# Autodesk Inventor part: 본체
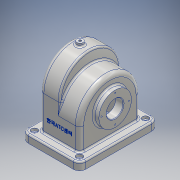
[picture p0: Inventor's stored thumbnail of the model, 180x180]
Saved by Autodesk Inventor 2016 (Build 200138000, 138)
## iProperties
Created: 2017-11
Part Number: 본체
Material: 알루미늄 6061
Document SubType Name: Modeling
Designer: USER
Density: 2.7 g/cm^3
Appearance: 알루미늄 - 평지
Mass: 1075.5 g
Surface Area: 1182.07 cm^2
Volume: 398.335 cm^3
Author: USER
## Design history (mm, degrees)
sketch "스케치1"
  geometry: L1 (-58, 0)-(-58, -80); L2 (58, 0)-(58, -80); L3 (58, -80)-(-58, -80); L4 (53, 0)-(53, -75); L5 (53, -75)-(-53, -75); L6 (-53, -75)-(-53, 0); A1 r 58 centre (0, 0) between (58, 0) and (-58, 0); A2 r 53 centre (0, 0) between (53, 0) and (-53, 0); 1 further point
  constraints: 12 end point, 4 point on circle, 2 centre point, 2 tangent, 2 vertical, 1 coincident, 3 other
  dimensions: "d0" = 116 diameter of A1; "d1" = 80 distance of L1.start L1.end; "d2" = 80 distance of L2.start L2.end; "d10" = 5 radial gap between concentric circles of A1 A2
node "작업 평면1"
extrude "돌출3" join sketch "스케치1" distance "d11" = 38; taper "d12" = 0 deg
sketch "스케치3"
  geometry: L1 (0, -58)-(80, -58) reference; L2 (0, -58)-(80, -58); L3 (80, 58)-(0, 58); L4 (80, 58)-(80, -58) reference; L5 (80, -58)-(80, 58); A1 r 58 centre (0, 0) between (0, 58) and (0, -58) reference; A2 r 58 centre (0, 0) between (0, 58) and (0, -58)
  constraints: 6 end point, 2 equal length, 2 point on circle, 2 point on line, 1 centre point, 1 coincident, 1 vertical
  dimensions: "d13" = 116 diameter of A2
extrude "돌출4" join sketch "스케치3" distance "d14" = 5; taper "d15" = 0 deg
sketch "스케치4"
  geometry: L1 (0, 58)-(-80, 58) reference; L2 (-80, 58)-(0, 58) reference; L3 (0, 58)-(-80, 58); L4 (0, -58)-(-80, -58) reference; L5 (-80, 58)-(-80, -58); L6 (-80, -58)-(0, -58); A1 r 58 centre (0, 0) between (0, -58) and (0, 58) reference; A2 r 58 centre (0, 0) between (0, -58) and (0, 58)
  constraints: 6 end point, 2 perpendicular, 2 point on circle, 2 point on line, 1 centre point, 1 coincident, 1 collinear
  dimensions: "d16" = 116 diameter of A2
extrude "돌출5" join sketch "스케치4" distance "d17" = 5; taper "d18" = 0 deg
sketch "스케치5"
  geometry: L1 (80, -58)-(80, 58) reference; L2 (80, -58)-(0, -58) reference; L3 (23, -58)-(80, -58); L4 (80, 58)-(80, -58) reference; L5 (80, -58)-(80, 58); L6 (80, 58)-(23, 58); L7 (0, 58)-(80, 58) reference; L8 (23, -53)-(75, -53); L9 (75, -53)-(75, 53); L10 (75, 53)-(23, 53); A1 r 58 centre (23, 0) between (23, 58) and (23, -58); A2 r 53 centre (23, 0) between (23, 53) and (23, -53)
  constraints: 12 end point, 4 point on circle, 2 centre point, 2 perpendicular, 2 point on line, 1 collinear, 1 tangent, 3 other
  dimensions: "d20" = 57 distance from line of A1.centre L1; "d21" = 58 radius of A1; "d22" = 5 radial gap between concentric circles of A1 A2
extrude "돌출6" join sketch "스케치5" distance "d23" = 38; taper "d24" = 0 deg
sketch "스케치6"
  geometry: L1 (23, -53)-(75, -53) reference; L2 (75, -53)-(75, 53) reference; L3 (75, 53)-(23, 53) reference; L4 (80, -58)-(0, -58) reference; L5 (0, 58)-(80, 58) reference; L6 (80, 58)-(80, -58) reference; L7 (80, -58)-(0, -58) reference; L8 (23, -58)-(80, -58); L9 (80, 58)-(23, 58); L10 (0, 58)-(80, 58) reference; L11 (80, 58)-(80, -58) reference; L12 (80, -58)-(80, 58); L13 (23, 53)-(75, 53); L14 (75, 53)-(75, -53); L15 (75, -53)-(23, -53); A1 r 53 centre (23, 0) between (23, 53) and (23, -53) reference; A2 r 58 centre (23, 0) between (23, 58) and (23, -58); A3 r 58 centre (0, 0) between (0, 58) and (0, -58) reference; A4 r 53 centre (23, 0) between (23, 53) and (23, -53); 1 further point
  constraints: 12 end point, 4 point on circle, 2 centre point, 2 point on line, 1 coincident, 1 collinear, 1 vertical, 3 other
  dimensions: "d25" = 116 diameter of A2; "d26" = 5 radial gap between concentric circles of A2 A4
extrude "돌출7" cut sketch "스케치6" distance "d27" = 5; taper "d28" = 0 deg
sketch "스케치7"
  geometry: L1 (80, -58)-(80, 58) reference; L2 (80, 58)-(23, 58) reference; L3 (0, -58)-(23, -58) reference; L4 (80, -58)-(0, -58) reference; L5 (23, -58)-(80, -58); L6 (80, -58)-(80, 58); L7 (23, 58)-(80, 58); A1 r 58 centre (23, 0) between (23, 58) and (23, -58) reference; A2 r 58 centre (23, 0) between (23, 58) and (23, -58); 1 further point
  constraints: 6 end point, 2 point on circle, 2 point on line, 1 centre point, 1 coincident, 1 collinear, 1 horizontal, 1 perpendicular
  dimensions: "d29" = 116 diameter of A2
extrude "돌출8" join sketch "스케치7" distance "d30" = 5; taper "d31" = 0 deg
sketch "스케치8"
  geometry: L1 (17, -17)-(-93, -17); L2 (-93, -17)-(-93, 133); L3 (-93, 133)-(17, 133); L4 (17, 133)-(17, -17); L5 (-5, 5)-(-71, 5); L6 (-71, 5)-(-71, 111); L7 (-71, 111)-(-5, 111); L8 (-5, 111)-(-5, 5); L9 (0, 116)-(0, 0) reference; L10 (0, 0)-(-76, 0) reference; L11 (-76, 0)-(-76, 116) reference; L12 (0, 116)-(-76, 116) reference; 10 further points
  constraints: 16 end point, 10 midpoint, 3 horizontal alignment, 3 vertical alignment, 2 parallel, 1 horizontal, 1 perpendicular
  dimensions: "d32" = 110 distance of L1.start L1.end; "d33" = 150 distance of L3.end L1.start; "d35" = 5 distance between parallel lines of L8 L9; "d36" = 5 distance between parallel lines of L10 L5
extrude "돌출9" join sketch "스케치8" distance "d37" = 15; taper "d38" = 0 deg
sketch "스케치9"
  geometry: L1 (88, 22)-(22, 22) reference; L2 (22, 22)-(22, 128) reference; L3 (88, 128)-(88, 22) reference; L4 (88, 128)-(22, 128) reference; L5 (22, 22)-(88, 22); L6 (88, 22)-(88, 128); L7 (88, 128)-(22, 128); L8 (22, 128)-(22, 22); 1 further point
  constraints: 8 end point, 2 parallel, 1 horizontal, 1 perpendicular
extrude "돌출10" cut sketch "스케치9" distance "d39" = 15; taper "d40" = 0 deg
node "작업 평면5"
  node "작업 평면4"
sketch "스케치10"
  geometry: C1 r 6 at (-74, 0); 1 further point
  constraints: 1 centre point, 1 horizontal alignment
  dimensions: "d42" = 12 diameter of C1; "d43" = 19 distance of point (-93, 0) C1.centre
extrude "돌출11" join sketch "스케치10" stored distance "d44" = 15; taper "d45" = 0 deg
sketch "스케치11"
  geometry: C1 r 6 at (0, 0) reference; 2 further points
  constraints: 1 coincident
hole "구멍1" sketch "스케치11" at (0, 0) diameter "d46" = 4.459; stored, may be unused: countersink angle "d50" = 90 deg, drill point angle "d52" = 118 deg; dims "d47" = 10, "d48" = 4, "d49" = 2, "d51" = 12.8
sketch "스케치13"
  geometry: L1 (80, -75)-(80, 75) reference; C1 r 31 at (15, 0); C2 r 16 at (15, 0); 1 further point
  constraints: 2 centre point, 1 coincident, 1 horizontal alignment
  dimensions: "d54" = 62 diameter of C1; "d55" = 32 diameter of C2; "d56" = 65 distance from line of C1.centre L1
extrude "돌출12" join sketch "스케치13" distance "d57" = 10; taper "d58" = 0 deg
sketch "스케치14"
  geometry: C1 r 16 at (0, 0) reference; C2 r 16 at (0, 0); 1 further point
  constraints: 1 centre point, 1 coincident
  dimensions: "d59" = 32 diameter of C2
extrude "돌출13" cut sketch "스케치14" distance "d60" = 85; taper "d61" = 0 deg
sketch "스케치15"
  geometry: L1 (-80, 75)-(-80, -75) reference; C1 r 37.5 at (-15, 0); C2 r 16 at (-15, 0); A1 r 58 centre (0, 0) between (0, -58) and (0, 58) reference
  constraints: 2 centre point, 1 coincident, 1 horizontal alignment
  dimensions: "d62" = 75 diameter of C1; "d63" = 32 diameter of C2; "d64" = 65 distance from line of C1.centre L1
extrude "돌출14" join sketch "스케치15" distance "d65" = 9; taper "d66" = 0 deg
sketch "스케치16"
  geometry: C1 r 16 at (0, 0) reference; 2 further points
  constraints: 1 horizontal alignment
  dimensions: "d67" = 26 distance of point (-26, 0) C1.centre
hole "구멍2" sketch "스케치16" at (-26, 0) diameter "d68" = 2.459; stored, may be unused: countersink angle "d72" = 90 deg, drill point angle "d74" = 118 deg; dims "d69" = 6, "d70" = 4, "d71" = 2, "d73" = 8
sketch "스케치17"
  geometry: C1 r 16 at (0, 0) reference; 2 further points
  constraints: 1 horizontal alignment
  dimensions: "d78" = 29 distance of point (29, 0) C1.centre
hole "구멍3" sketch "스케치17" at (29, 0) diameter "d79" = 2.459; stored, may be unused: countersink angle "d83" = 90 deg, drill point angle "d85" = 118 deg; dims "d80" = 6, "d81" = 4, "d82" = 2, "d84" = 8
sketch "스케치19"
  geometry: L1 (0, -65)-(0, 0) reference; L2 (-17, -80)-(93, -80) reference; L3 (-17, -80)-(-17, -65) reference; L4 (-17, -65)-(93, -65) reference; 1 further point
  constraints: 1 other
  dimensions: "d93" = 40 distance from line of point (38, -40) L2; "d94" = 38 distance from line of point (38, -40) L1
feature "엠보싱1" sketch "스케치19" dims "d95" = 0.5, "d96" = 0
fillet "모깎기1" dims "d97" = 12
fillet "모깎기2" dims "d98" = 8
fillet "모깎기3" dims "d99" = 3
chamfer "모따기1" distance "d100" = 1; stored, may be unused: second distance "d101" = 2, angle "d102" = 45 deg
fillet "모깎기4" dims "d103" = 3
sketch "스케치20"
  geometry: A1 r 9 centre (81, -5) between (81, -14) and (90, -5) reference; A2 r 9 centre (81, 121) between (90, 121) and (81, 130) reference; A3 r 9 centre (-5, 121) between (-5, 130) and (-14, 121) reference; A4 r 9 centre (-5, -5) between (-14, -5) and (-5, -14) reference; 5 further points
  constraints: 4 coincident
hole "구멍4" sketch "스케치20" at (-5, -5), (81, -5), (81, 121), (-5, 121) diameter "d104" = 5; stored, may be unused: countersink angle "d108" = 90 deg, drill point angle "d110" = 0 deg; dims "d105" = 6, "d106" = 12, "d107" = 5, "d109" = 8
node "솔리드1"
pattern_circular "원형 패턴1" dims angle "d76" = 360 deg
pattern_circular "원형 패턴2" dims angle "d87" = 360 deg
node "투영된 루프1"
other parameters: "d5" = 116, "d19" = 116, "d41" = 144
